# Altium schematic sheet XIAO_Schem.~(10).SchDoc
size A; SheetNumber: 1; SheetTotal: 1
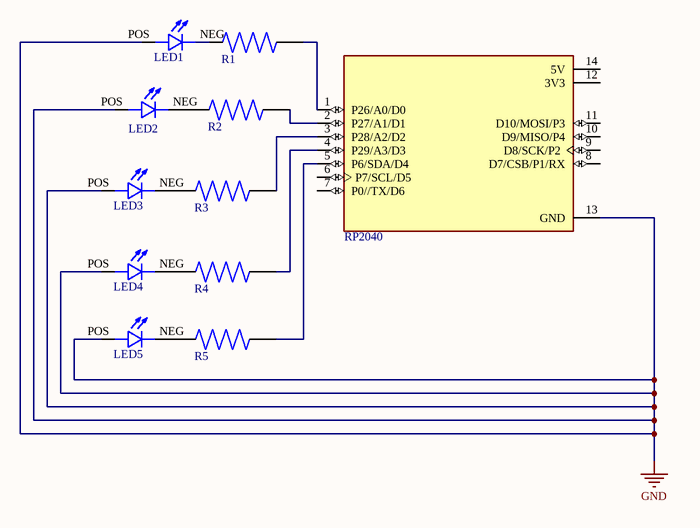
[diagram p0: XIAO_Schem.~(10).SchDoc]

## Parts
LED1  LHN974_RED_LED_1206  [LED2]  (value not drawn)
LED2  LHN974_RED_LED_1206  [LED2]  (value not drawn)
LED3  LHN974_RED_LED_1206  [LED2]  (value not drawn)
LED4  LHN974_RED_LED_1206  [LED2]  (value not drawn)
LED5  LHN974_RED_LED_1206  [LED2]  (value not drawn)
R1  1k  [1k]  (value not drawn)
R2  1k  [1k]  (value not drawn)
R3  1k  [1k]  (value not drawn)
R4  1k  [1k]  (value not drawn)
R5  1k  [1k]  (value not drawn)
RP2040  102010428  [102010428]  (value not drawn)

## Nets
GND: LED1.POS LED2.POS LED3.POS LED4.POS LED5.POS RP2040.13(GND)
NetLED1_NEG: LED1.NEG R1.1
NetLED2_NEG: LED2.NEG R2.1
NetLED3_NEG: LED3.NEG R3.1
NetLED4_NEG: LED4.NEG R4.1
NetLED5_NEG: LED5.NEG R5.1
NetR1_2: R1.2 RP2040.1(P26/A0/D0)
NetR2_2: R2.2 RP2040.2(P27/A1/D1)
NetR3_2: R3.2 RP2040.3(P28/A2/D2)
NetR4_2: R4.2 RP2040.4(P29/A3/D3)
NetR5_2: R5.2 RP2040.5(P6/SDA/D4)

Not connected (* = marked no-connect by the designer): RP2040 6(P7/SCL/D5) 7(P0//TX/D6) 8(D7/CSB/P1/RX) 9(D8/SCK/P2) 10(D9/MISO/P4) 11(D10/MOSI/P3) 12(3V3) 14(5V)

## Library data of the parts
LED1-LED5 = LED2: 2.6 V Red LED SMD; MP: LHN974 RED LED 1206; MF: Osram
R1-R5 = 1k: Res Thick Film 3.2 x 1.6 mm 6.8K Ohm 1% 0.25W(1/4W) 100ppm/ C Molded SMD Paper T/R; MP: RC1206FR-076K8L
RP2040 = 102010428: RP2040 XIAO RP2040 series ARMÂ® CortexÂ®-M0+ MCU 32-Bit Embedded Evaluation Board; MF: Seeed Technology Co., Ltd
